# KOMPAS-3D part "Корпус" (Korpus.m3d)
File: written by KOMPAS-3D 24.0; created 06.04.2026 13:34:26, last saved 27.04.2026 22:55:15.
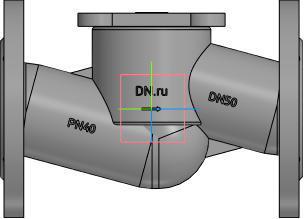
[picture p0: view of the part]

Document properties: Автор: R2D2; Полное имя файла: C:\Работа\ГОТОВЫЕ ИСХОДНИКИ\VSO2130M-F-S Клапан запорный сильфонный DN.ru Ду15-100 Ру40\исходные материалы\DN50\Korpus.m3d

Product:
- Body: Труба / Нестандартная труба / L = 147.7 мм  | qty 1  | 2 such rows
    Материал: Нестандартная труба (density 7856 kg/m3)
    Масса: 14.283601
    Раздел спецификации: Детали
    Примечание: 4,47 кг
    additional columns: Pipeline; 0.07; 0; 0; 0.002; 0.14772; true; 0.04
- Body: Тело 4  | qty 1
    Материал: Нестандартная труба (density 7856 kg/m3)
    Масса: 14.283601
- Body: Тело 5  | qty 1
    Материал: Нестандартная труба (density 7856 kg/m3)
    Масса: 14.283601
- Body: Тело 8  | qty 1
    Материал: Нестандартная труба (density 7856 kg/m3)
    Масса: 14.283601
- Body: Тело 10  | qty 1
    Материал: Нестандартная труба (density 7856 kg/m3)
    Масса: 14.283601
- Body: Тело 11  | qty 1
    Материал: Нестандартная труба (density 7856 kg/m3)
    Масса: 14.283601
- Body: Тело 12  | qty 1
    Материал: Нестандартная труба (density 7856 kg/m3)
    Масса: 14.283601
- Body: Тело 13  | qty 1
    Материал: Нестандартная труба (density 7856 kg/m3)
    Масса: 14.283601
- Part/product: Корпус
    Масса: 6.9

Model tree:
1. Труба:1  (labels: {F703FF30-5BE6-4673-A7F1-8EDA1BE1E2D1}; SHAPEOBJECT3D_ATTR_BUTT; SHAPEOBJECT3D_ATTR_VALID; SHAPEOBJECT3D_ATTR_BUTT_AREA)
     PIPE_R = 3
2. Труба:2  (labels: {F703FF30-5BE6-4673-A7F1-8EDA1BE1E2D1}; SHAPEOBJECT3D_ATTR_BUTT; SHAPEOBJECT3D_ATTR_VALID; SHAPEOBJECT3D_ATTR_BUTT_AREA)
     PIPE_R = 3
3. Колонна
4. Элемент выдавливания:1
     Смещение 1 = -1; Смещение 2 = -5
5. Скругление:17  (with: Ребро.Элемент выдавливания:1)
     Радиус = 2
6. Скругление:18  (with: Ребро.Элемент выдавливания:1)
7. Скругление:24
     Радиус = 1.5
8. Элемент выдавливания:2
     Расстояние 1 = 6
9. Эскиз:4  (with: Грань.Элемент выдавливания:1)
10. Элемент выдавливания:3
     Расстояние 1 = 0.5
11. ОТЛИВКА
12. Скругление:6  (with: Грань.Элемент выдавливания:1)
     Радиус = 2
13. Элемент выдавливания:6  (with: Грань.Элемент выдавливания:1)
     Смещение 1 = 4
14. ЛЕЙБЛ
15. Элемент выдавливания:7  (with: Грань.Элемент выдавливания:1)
     Расстояние 1 = 45.9793; Смещение 1 = 1
16. Dn
17. Pn
18. Стрелочка
19. Элемент выдавливания:10  (with: Грань.Труба:1)
     Расстояние 1 = 35.8203; Смещение 1 = 1
20. Элемент выдавливания:11  (with: Грань.Труба:2)
     Расстояние 1 = 35.9787; Смещение 1 = 1
21. Элемент выдавливания:12  (with: Грань.Элемент выдавливания:1)
     Расстояние 1 = 45.9998; Смещение 1 = 1
22. Материал
23. Элемент выдавливания:13  (with: Грань.Элемент выдавливания:1)
     Расстояние 1 = 45.4944; Смещение 1 = 0.5
24. Фланец верх  (with: Грань.Элемент выдавливания:3)
25. Элемент выдавливания:14
     Расстояние 1 = 10
26. Эскиз:18  (with: Грань.Элемент выдавливания:14)
27. Элемент выдавливания:15
     Расстояние 1 = 0.5
28. Эскиз:19  (with: Грань.Элемент выдавливания:14, Ребро.Элемент выдавливания:14)
29. Элемент выдавливания:16  (with: Грань.Элемент выдавливания:14)
     Расстояние 1 = 0.5; Расстояние 2 = 11; Смещение 2 = 1
30. Фланец
31. Элемент вращения:1
     Угол 1 = 360
32. отвертие во фланце  (with: Грань.Элемент вращения:1)
33. Элемент выдавливания:8
34. Массив по концентрической сетке:2  (with: Элемент выдавливания:8, Эскиз:10, Грань.Элемент вращения:1)  (4 pattern instances)
     Шаг 2 = 360
35. Зеркальный массив:1
36. Экземпляр ( 1 )
37. Экземпляр ( 2 )  (with: Элемент вращения:1, Массив по концентрической сетке:2, Экземпляр ( 1 ), Элемент выдавливания:8)
38. Экземпляр ( 3 )  (with: Элемент выдавливания:8)
39. Экземпляр ( 4 )  (with: Элемент выдавливания:8)
40. Массив по концентрической сетке:3  (with: Элемент выдавливания:16, Эскиз:19)  (labels: Клапан запорный DN.ru Ду50 Ру40)  (4 pattern instances)
     Шаг 2 = 360
41. Скругление:25  (with: Ребро.Элемент выдавливания:1)
     Радиус = 2

Expressions: DS/2+3; DN/2; LL/2; D1/2; D2/2-10
Referenced files in C:\Работа\ГОТОВЫЕ ИСХОДНИКИ\VSO2130M-F-S Клапан запорный сильфонный DN.ru Ду15-100 Ру40\исходные материалы\DN50\: VSO2130M-F-S Клапан запорный DN.ru Ду50 Ру40.a3d
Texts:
  GOST 26.020 Pr3
  var3D
  GS-C25
  смещение колонны вниз
  LL-10
  DN+20
  DS+15
  Труба / Нестандартная труба / L = %s мм
  Ось Y.Начало координат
